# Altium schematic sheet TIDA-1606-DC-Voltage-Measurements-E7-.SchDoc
size 431 x 279 mm; Date: Not shown in title block; ApprovedBy: Not shown in title block; CheckedBy: Not shown in title block; Author: Not shown in title block; CompanyName: Not shown in title block; Engineer: Not shown in title block; Organization: Not shown in title block; Address1: Not shown in title block; Address2: Not shown in title block; Address3: Not shown in title block; Address4: Not shown in title block; DocumentNumber: 8; Revision: Use project parameter SCH_Rev; SheetNumber: 8; SheetTotal: 16; PageSetup: Record=PageOptions¦CenterHorizontal=True¦CenterVertical=True¦PrintScale=1.00¦XCorrection=1.00¦YCorrection=1.00¦PrintKind=0¦BorderSize=5000000¦LeftOffset=0¦BottomOffset=0¦Orientation=2¦PaperLength=1000¦PaperWidth=1000¦Scale=100¦PaperSource=15¦PrintQuality=600¦MediaType=1¦DitherType=10¦PaperKind=Letter¦PrintScaleMode=1
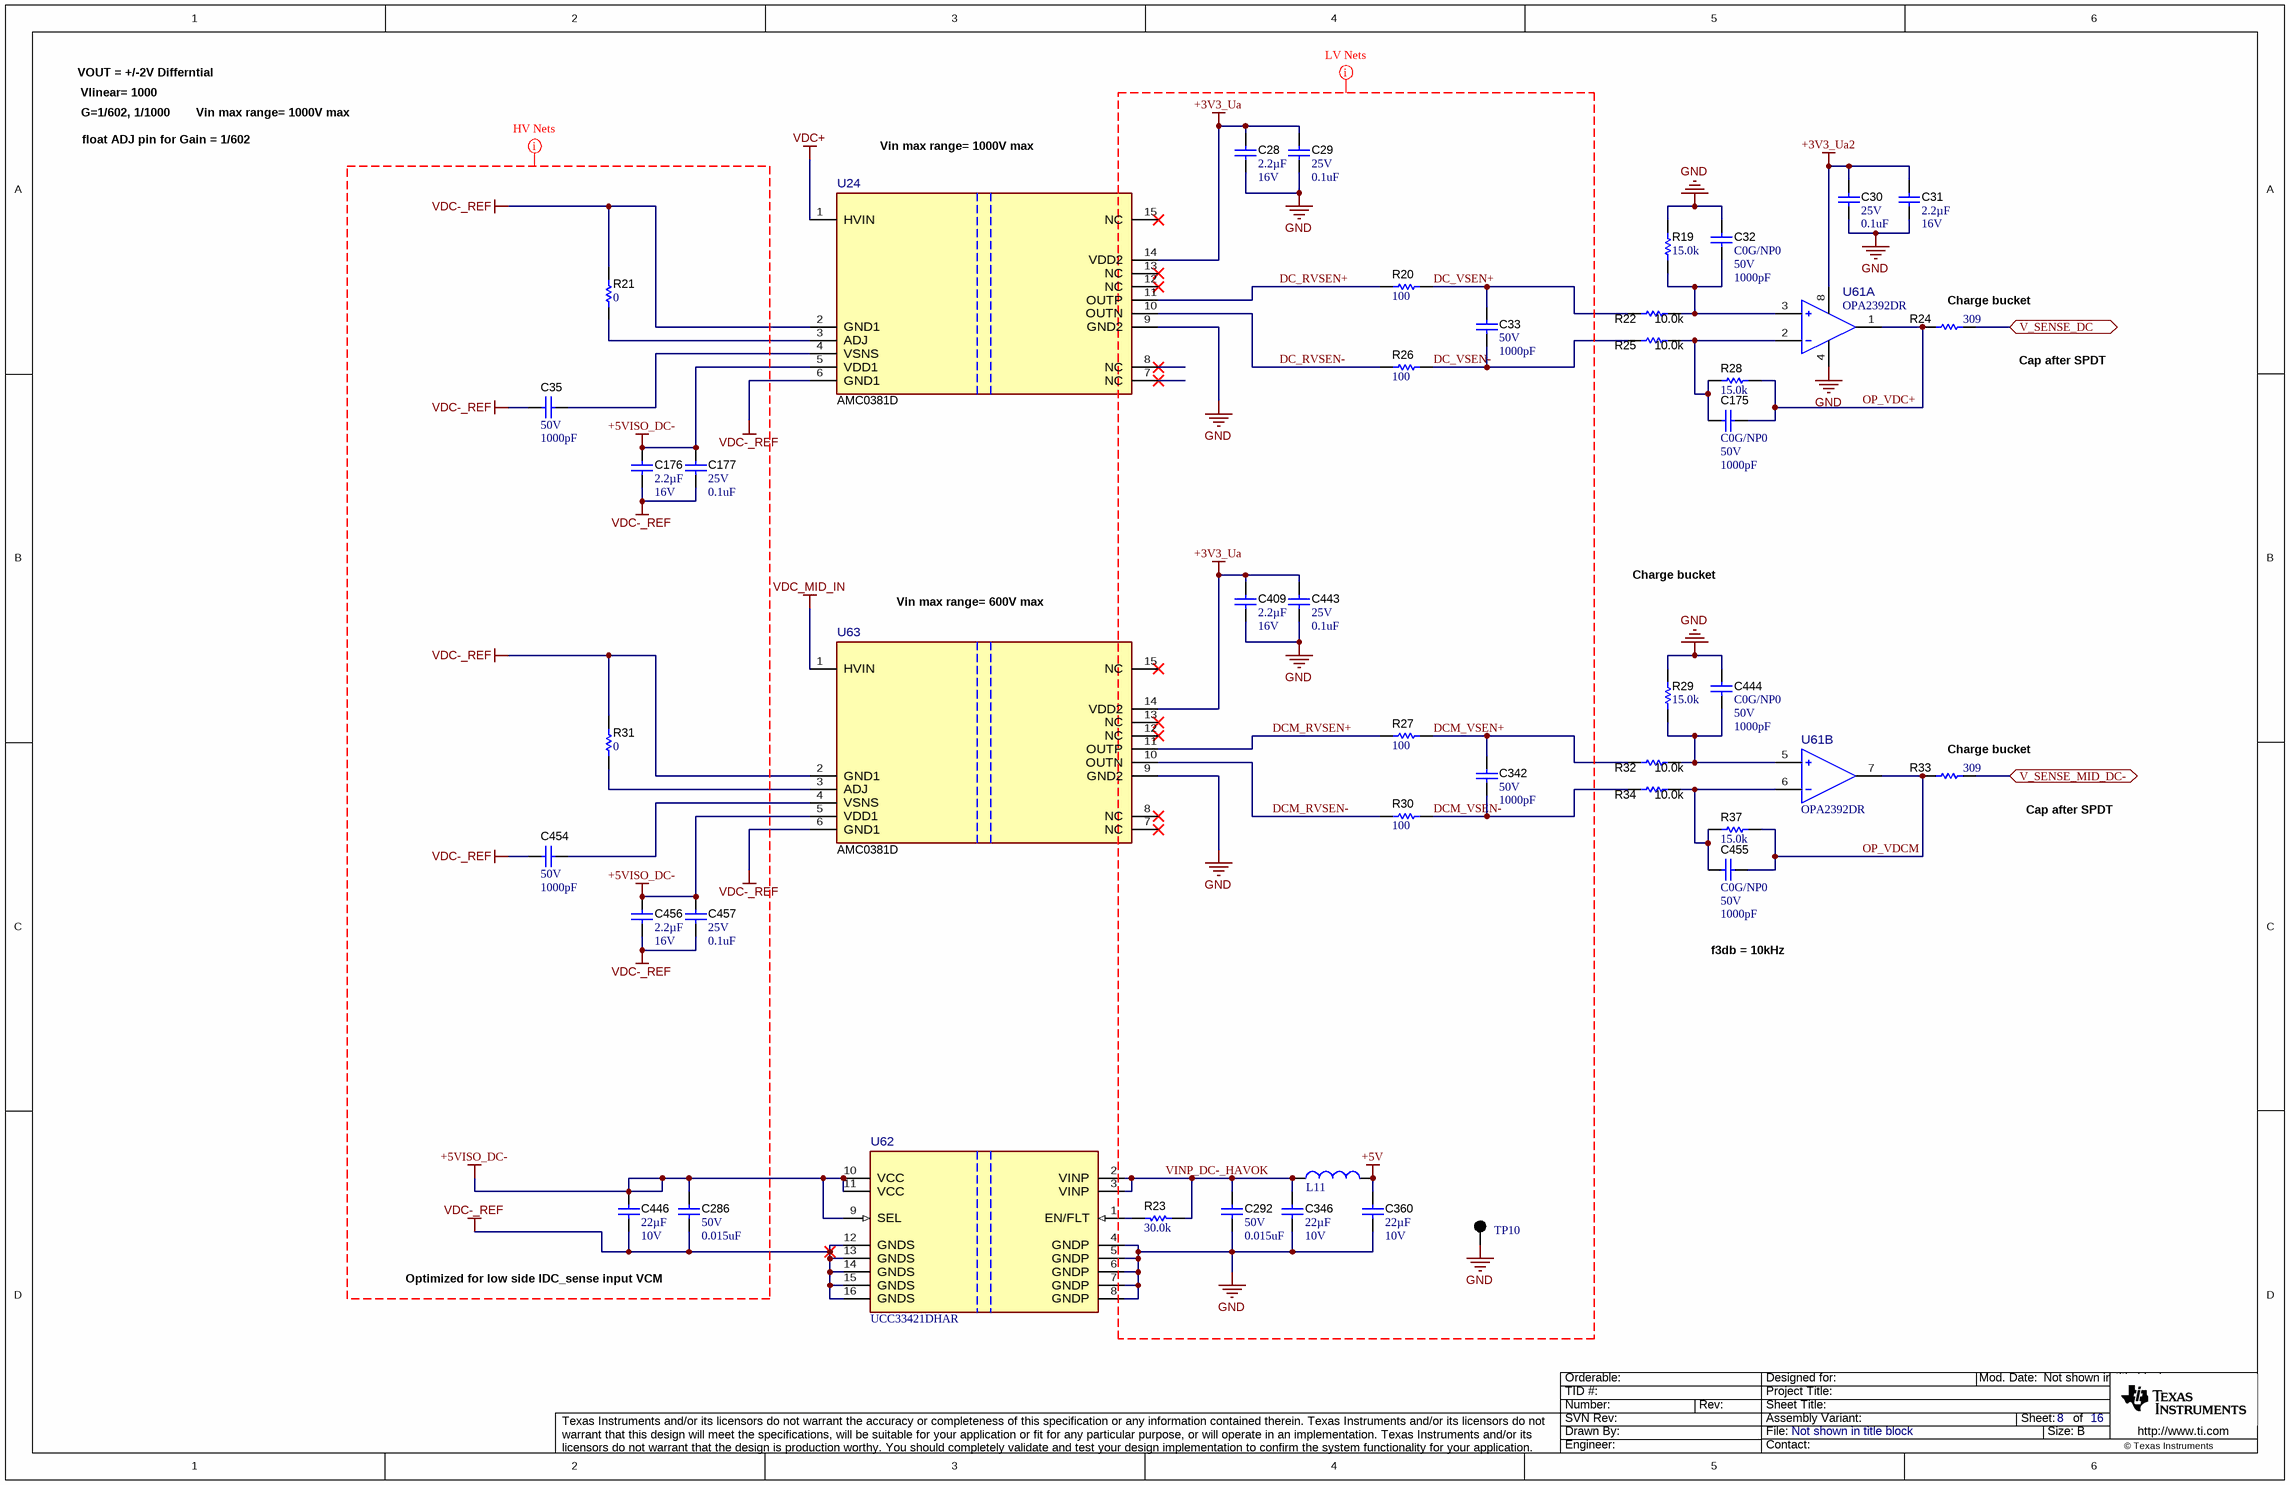
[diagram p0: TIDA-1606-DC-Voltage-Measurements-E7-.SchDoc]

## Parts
C28  Cap_F: 2.2µF  VDC_V: 16V  [0603]  (hidden comment: EMK107BB7225KA-T)
C29  VDC_V: 25V  ValueDisplayed: 0.1uF  [0402L]  (hidden comment: GRM155R71E104KE14D)
C30  VDC_V: 25V  ValueDisplayed: 0.1uF  [0402L]  (hidden comment: GRM155R71E104KE14D)
C31  Cap_F: 2.2µF  VDC_V: 16V  [0603]  (hidden comment: EMK107BB7225KA-T)
C32  TempCo: C0G/NP0  VDC_V: 50V  ValueDisplayed: 1000pF  [0402L]  (hidden comment: CGA2B2C0G1H102J050BA)
C33  VDC_V: 50V  ValueDisplayed: 1000pF  [0402L]  (hidden comment: GRM1555C1H102JA01D)
C35  VDC_V: 50V  ValueDisplayed: 1000pF  [0402L]  (hidden comment: GRM155R71H102KA01D)
C175  TempCo: C0G/NP0  VDC_V: 50V  ValueDisplayed: 1000pF  [0402L]  (hidden comment: CGA2B2C0G1H102J050BA)
C176  Cap_F: 2.2µF  VDC_V: 16V  [0603]  (hidden comment: EMK107BB7225KA-T)
C177  VDC_V: 25V  ValueDisplayed: 0.1uF  [0402L]  (hidden comment: GRM155R71E104KE14D)
C286  VDC_V: 50V  ValueDisplayed: 0.015uF  [0402L]  (hidden comment: CGA2B3X7R1H153K050BB)
C292  VDC_V: 50V  ValueDisplayed: 0.015uF  [0402L]  (hidden comment: CGA2B3X7R1H153K050BB)
C342  VDC_V: 50V  ValueDisplayed: 1000pF  [0402L]  (hidden comment: GRM1555C1H102JA01D)
C346  Cap_F: 22µF  VDC_V: 10V  [0805_HV]  (hidden comment: GRM21BZ71A226ME15L)
C360  Cap_F: 22µF  VDC_V: 10V  [0805_HV]  (hidden comment: GRM21BZ71A226ME15L)
C409  Cap_F: 2.2µF  VDC_V: 16V  [0603]  (hidden comment: EMK107BB7225KA-T)
C443  VDC_V: 25V  ValueDisplayed: 0.1uF  [0402L]  (hidden comment: GRM155R71E104KE14D)
C444  TempCo: C0G/NP0  VDC_V: 50V  ValueDisplayed: 1000pF  [0402L]  (hidden comment: CGA2B2C0G1H102J050BA)
C446  Cap_F: 22µF  VDC_V: 10V  [0805_HV]  (hidden comment: GRM21BZ71A226ME15L)
C454  VDC_V: 50V  ValueDisplayed: 1000pF  [0402L]  (hidden comment: GRM155R71H102KA01D)
C455  TempCo: C0G/NP0  VDC_V: 50V  ValueDisplayed: 1000pF  [0402L]  (hidden comment: CGA2B2C0G1H102J050BA)
C456  Cap_F: 2.2µF  VDC_V: 16V  [0603]  (hidden comment: EMK107BB7225KA-T)
C457  VDC_V: 25V  ValueDisplayed: 0.1uF  [0402L]  (hidden comment: GRM155R71E104KE14D)
L11  74479763222  [WE-PMI_0603_L1.6W0.8H0.8]  (value not drawn)
R19  ValueDisplayed: 15.0k  [0402L]  (hidden comment: ERA-2AEB153X)
R20  ValueDisplayed: 100  [0402L]  (hidden comment: ERJ-2RKF1000X)
R21  ValueDisplayed: 0  [0402L]  (hidden comment: RC0402JR-070RL)
R22  ValueDisplayed: 10.0k  [0402L]  (hidden comment: MCS0402MD1002BE100)
R23  ValueDisplayed: 30.0k  [0402L]  (hidden comment: CRCW040230K0FKED)
R24  ValueDisplayed: 309  [0402L]  (hidden comment: CRCW0402309RFKED)
R25  ValueDisplayed: 10.0k  [0402L]  (hidden comment: MCS0402MD1002BE100)
R26  ValueDisplayed: 100  [0402L]  (hidden comment: ERJ-2RKF1000X)
R27  ValueDisplayed: 100  [0402L]  (hidden comment: ERJ-2RKF1000X)
R28  ValueDisplayed: 15.0k  [0402L]  (hidden comment: ERA-2AEB153X)
R29  ValueDisplayed: 15.0k  [0402L]  (hidden comment: ERA-2AEB153X)
R30  ValueDisplayed: 100  [0402L]  (hidden comment: ERJ-2RKF1000X)
R31  ValueDisplayed: 0  [0402L]  (hidden comment: RC0402JR-070RL)
R32  ValueDisplayed: 10.0k  [0402L]  (hidden comment: MCS0402MD1002BE100)
R33  ValueDisplayed: 309  [0402L]  (hidden comment: CRCW0402309RFKED)
R34  ValueDisplayed: 10.0k  [0402L]  (hidden comment: MCS0402MD1002BE100)
R37  ValueDisplayed: 15.0k  [0402L]  (hidden comment: ERA-2AEB153X)
TP10  5011  [Keystone5011]  (value not drawn)
U24  AMC0381D  [DFX0015A-MFG]
U61  OPA2392DR  [D0008A-MFG]  (parts A,B of 2)
U62  UCC33421DHAR  [DHA0016A-MFG]
U63  AMC0381D  [DFX0015A-MFG]

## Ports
V_SENSE_DC (bidir), V_SENSE_MID_DC- (bidir)

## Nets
+3V3_Ua: C28.2 C29.1 C409.2 C443.1 U24.14(VDD2) U63.14(VDD2)
+3V3_Ua2: C30.1 C31.1 U61.8(V+)
+5V: C360.1 L11.2
+5VISO_DC-: C176.2 C177.1 C286.1 C446.1 C456.2 C457.1 U24.5(VDD1) U62.9(SEL) U62.10(VCC) U62.11(VCC) U63.5(VDD1)
GND: C28.1 C29.2 C30.2 C31.2 C32.1 C292.2 C346.2 C360.2 C409.1 C443.2 C444.1 R19.2 R29.2 TP10.1 U24.9(GND2) U61.4(V-) U62.4(GNDP) U62.5(GNDP) U62.6(GNDP) U62.7(GNDP) U62.8(GNDP) U63.9(GND2)
VDC+: U24.1(HVIN)
VDC-_REF: C35.1 C176.1 C177.2 C286.2 C446.2 C454.1 C456.1 C457.2 R21.2 R31.2 U24.2(GND1) U24.6(GND1) U62.12(GNDS) U62.13(GNDS) U62.14(GNDS) U62.15(GNDS) U62.16(GNDS) U63.2(GND1) U63.6(GND1)
VDC_MID_IN: U63.1(HVIN)
DC_RVSEN+: R20.1 U24.11(OUTP)
DC_RVSEN-: R26.1 U24.10(OUTN)
DC_VSEN+: C33.1 R20.2 R22.2
DC_VSEN-: C33.2 R25.2 R26.2
DCM_RVSEN+: R27.1 U63.11(OUTP)
DCM_RVSEN-: R30.1 U63.10(OUTN)
DCM_VSEN+: C342.1 R27.2 R32.2
DCM_VSEN-: C342.2 R30.2 R34.2
OP_VDC+: C175.2 R24.1 R28.2 U61.1(OUT_A)
OP_VDCM: C455.2 R33.1 R37.2 U61.7(OUT_B)
V_SENSE_DC: R24.2 ; port V_SENSE_DC
V_SENSE_MID_DC-: R33.2 ; port V_SENSE_MID_DC-
VINP_DC-_HAVOK: C292.1 C346.1 L11.1 R23.1 U62.2(VINP) U62.3(VINP)
NetC32_2: C32.2 R19.1 R22.1 U61.3(+IN_A)
NetC35_2: C35.2 U24.4(VSNS)
NetC175_1: C175.1 R25.1 R28.1 U61.2(-IN_A)
NetC444_2: C444.2 R29.1 R32.1 U61.5(+IN_B)
NetC454_2: C454.2 U63.4(VSNS)
NetC455_1: C455.1 R34.1 R37.1 U61.6(-IN_B)
NetR21_1: R21.1 U24.3(ADJ)
NetR23_2: R23.2 U62.1(EN/FLT)
NetR31_1: R31.1 U63.3(ADJ)

Not connected (* = marked no-connect by the designer): U24 7(NC)* 8(NC)* 12(NC)* 13(NC)* 15(NC)*; U63 7(NC)* 8(NC)* 12(NC)* 13(NC)* 15(NC)*

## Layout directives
net class LV Nets: +3V3_Ua, +5V, DC_RVSEN+, DC_RVSEN-, DC_VSEN+, DC_VSEN-, DCM_RVSEN+, DCM_RVSEN-, DCM_VSEN+, DCM_VSEN-, GND, VINP_DC-_HAVOK
net class HV_Nets; net class HV_VDC_LOW: +5VISO_DC-, VDC-_REF

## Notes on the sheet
- Vlinear= 1000
- VOUT = +/-2V Differntial
- G=1/602, 1/1000
- float ADJ pin for Gain = 1/602
- Vin max range= 1000V max
- (near R24) Charge bucket
- Cap after SPDT
- Charge bucket
- Vin max range= 600V max
- (near R33) Charge bucket
- f3db = 10kHz
- Optimized for low side IDC_sense input VCM

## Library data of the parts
C28 C31 C176 C409 C456 = CMP-0007121-4: CAP, CERM, 2.2 uF, 16 V, +/- 10%, X7R, 0603; Manufacturer: Taiyo Yuden; TaMin_C: -55°C; Polarized: N; SizeAreaWB_mm2: 4.68; Value1: Unknown; U/M: EA; Value: 2.2uF; TaMax_C: 125°C; SizeZ_mm: 1; SizeX_mm: 1.6; SizeY_mm: 0.8; SizeArea_mm2: 1.28; AEC Category: Q200
C29 C30 C177 C443 C457 = CMP-0006659-2: CAP, CERM, 0.1 uF, 25 V, +/- 10%, X7R, 0402; Manufacturer: MuRata; TaMin_C: -55°C; Polarized: N; SizeAreaWB_mm2: 3; Value1: Unknown; U/M: EA; Value: 0.1uF; TaMax_C: 125°C; SizeZ_mm: 0.6; SizeX_mm: 1; SizeY_mm: 0.5; Cap_Case: 0402; Cap_F: 100nF; AEC Category: Q200
C32 C175 C444 C455 = CMP-0006309-2: CAP, CERM, 1000 pF, 50 V, +/- 5%, C0G/NP0, AEC-Q200 Grade 1, 0402; Manufacturer: TDK; TaMin_C: -55°C; Polarized: N; SizeAreaWB_mm2: 3; Value1: Unknown; U/M: EA; Value: 1000pF; TaMax_C: 125°C; SizeZ_mm: 0.6; SizeX_mm: 1; SizeY_mm: 0.5; Cap_Case: 0402; AEC Qualified: Y; Cap_F: 1nF; AEC Category: Q200
C33 C342 = CMP-0006412-2: CAP, CERM, 1000 pF, 50 V, +/- 5%, C0G/NP0, 0402; Manufacturer: MuRata; TaMin_C: -55°C; Polarized: N; SizeAreaWB_mm2: 3; Value1: Unknown; U/M: EA; Value: 1000pF; TaMax_C: 125°C; SizeZ_mm: 0.6; SizeX_mm: 1; SizeY_mm: 0.5; Cap_Case: 0402; Cap_F: 1nF; AEC Category: Q200
C35 C454 = CMP-0006673-2: CAP, CERM, 1000 pF, 50 V, +/- 10%, X7R, 0402; Manufacturer: MuRata; TaMin_C: -55°C; Polarized: N; SizeAreaWB_mm2: 3; Value1: Unknown; U/M: EA; Value: 1000pF; TaMax_C: 125°C; SizeZ_mm: 0.6; SizeX_mm: 1; SizeY_mm: 0.5; Cap_Case: 0402; Cap_F: 1nF; AEC Category: Q200
C286 C292 = CMP-0006327-2: CAP, CERM, 0.015 uF, 50 V, +/- 10%, X7R, AEC-Q200 Grade 1, 0402; Manufacturer: TDK; TaMin_C: -55°C; ESR_ohm: 0.2162; Polarized: N; SizeAreaWB_mm2: 3; Value1: 0.2162 ohm; U/M: EA; TaMax_C: 125°C; SizeZ_mm: 0.6; SizeX_mm: 1; SizeY_mm: 0.5; Cap_Case: 0402; AEC Qualified: Y; Cap_F: 15nF; IRMS_A: 379.389mA; AEC Category: Q200
C346 C360 C446 = CMP-0008377-2: CAP, CERM, 22 uF, 10 V, +/- 20%, X7R, 0805; Manufacturer: MuRata; SizeY_mm: 1.25; Cap_Case: 0805; SizeArea_mm2: 2.5; AEC Qualified: N; AEC Category: Q200; ValueDisplayed: 22uF; TaMin_C: -55°C; SizeAreaWB_mm2: 6.75; Value1: Unknown; U/M: EA; Value: 22uF; TaMax_C: 125°C; SizeZ_mm: 1.45; SizeX_mm: 2
L11 = CMP-0100992-1: WE-PMI SMT Power Multilayer Inductor, size 0603, 2.2uH, 0.8A, 375mOhm; Manufacturer: Wurth Elektronik; Case/Size Code: 0603; Inductance Tolerance: 20%; Q Factor: 15; Saturation Current: 0.28A; Self Resonant Frequency: 80MHz; Type: Low RDC
R19 R28 R29 R37 = CMP-0065359-1: RES, 15.0 k, .1%, .063 W, AEC-Q200 Grade 0, 0402; Manufacturer: Panasonic; Power_W: 63mW; TempCo: 25 ppm/C; Value_Code: 15k0; U/M: EA; Value: 15.0k; EIA_Code: E192; Tolerance_%: 0.1%; Res_ohm: 15k; SizeX_mm: 1.0; SizeY_mm: 0.5; SizeZ_mm: 0.6; Value2: .063W; AEC Qualified: Y; VDC_V: 50V; AEC Grade: 0; AEC Category: Q200
R20 R26 R27 R30 = CMP-0026656-1: RES, 100, 1%, 0.1 W, 0402; Manufacturer: Panasonic; Power_W: 100mW; TempCo: 100 ppm/C; Value_Code: 100R; U/M: EA; Value: 100; EIA_Code: E96; SizeX_mm: 1; SizeY_mm: 0.5; SizeZ_mm: 0.6; Value2: 0.1W; VDC_V: 50V; AEC Category: Q200
R21 R31 = CMP-0027004-2: RES, 0, 5%, 0.063 W, 0402; Manufacturer: Yageo America; Power_W: 63mW; TempCo: 200 ppm/C; Value_Code: 0000; U/M: EA; Value: 0; EIA_Code: E24; SizeX_mm: 1; SizeY_mm: 0.5; SizeZ_mm: 0.6; Value2: 0.063W; VDC_V: 50V; AEC Category: Q200
R22 R25 R32 R34 = CMP-0077124-1: RES, 10.0 k, 0.1%, 0.1 W, AEC-Q200 Grade 0, 0402; Manufacturer: Vishay/Beyschlag; Value_Code: 10k0; SizeArea_mm2: 0.5; AEC Qualified: Y; AEC Category: Q200; Res_ohm: 10k; Value: 10.0k; SizeZ_mm: 0.6; EIA_Code: E192; TempCo: 25 ppm/C; AEC Grade: 0; Power_W: 100mW; VDC_V: 50V; Value2: 0.1W; U/M: EA; SizeX_mm: 1.0
R23 = CMP-0078244-2: RES, 30.0 k, 1%, 0.063 W, AEC-Q200 Grade 0, 0402; Manufacturer: Vishay-Dale; Power_W: 63mW; Green_Lifecycle: Active; TempCo: 100 ppm/C; Value_Code: 30k0; Green_REACh: Passed; Value: 30.0k; Res_ohm: 30k; SizeX_mm: 1; SizeY_mm: 0.5; SizeZ_mm: 0.6; Value2: 0.063W; AEC Qualified: Y; VDC_V: 50V; AEC Grade: 0; AEC Category: Q200
R24 R33 = CMP-0026283-2: RES, 309, 1%, 0.063 W, AEC-Q200 Grade 0, 0402; Manufacturer: Vishay-Dale; Power_W: 63mW; TempCo: 100 ppm/C; Value_Code: 309R; Value: 309; EIA_Code: E96; SizeX_mm: 1; SizeY_mm: 0.5; SizeZ_mm: 0.6; Value2: 0.063W; AEC Qualified: Y; VDC_V: 50V; AEC Category: Q200; AEC Grade: 0
TP10 = CMP-0055148-2: Test Point, Multipurpose, Black, TH; Manufacturer: Keystone Electronics; CNHeader: FALSE; ContactFinish: Silver; Green_REACh: Passed; Green_Lifecycle: Active; CT: TRUE
U24 U63 = CMP-0044881-2: Manufacturer: Texas Instruments; SizeZ_mm: 3.55mm; Standoff Height: 0.1mm; AEC Category: Q200; CompType: IC
U61 = CMP-0121707-1: Precision, Low-Offset-Voltage, Low-Noise, Low-Input-Bias-Current, Rail-to-Rail I/O, e-trim™ Operational Amplifiers; Manufacturer: Texas Instruments; SizeZ_mm: 1.75mm; AEC Qualified: No; Gain Bandwidth: 13MHz; Input Bias Current: 0.00000001uA; Input Offset Voltage: 0.001mV; Max Dual Supply Voltage: 2.75V; Max Supply Voltage: 5.5V; Min Dual Supply Voltage: 850mV; Min Supply Voltage: 1.7V; Nominal Supply Current: 1.22mA; Number Of Channels: 2; Output Current Per Channel: 65mA; Response Time: 1us; Standoff Height: 0.11mm; TaMax_C: +125°C; TaMin_C: -40°C; TJmax_C: +150°C; Voltage Gain: 132dB
U62 = CMP-0123146-1: Ultra-Small, 1.5W, 5.0V, 5kVRMS Isolation, Industrial DC/DC Module; Manufacturer: Texas Instruments; SizeZ_mm: 2.6mm; AEC Qualified: No; Max Supply Voltage: 5.5V; Min Supply Voltage: 4.5V; Nominal Supply Current: 7-545mA; Number Of Outputs: 1; Output Type: AdjustableProgrammable; Output Voltage: 5/5.5V; Standoff Height: 0.1mm; Switching Frequency: 76MHz; Switching Topology: Boost; TaMax_C: +125°C; TaMin_C: -40°C; TJmax_C: +150°C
